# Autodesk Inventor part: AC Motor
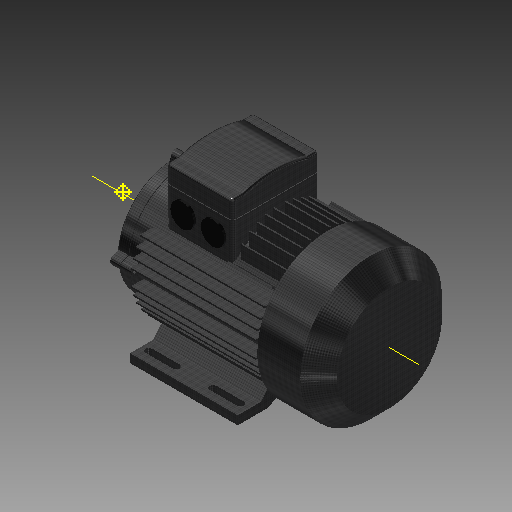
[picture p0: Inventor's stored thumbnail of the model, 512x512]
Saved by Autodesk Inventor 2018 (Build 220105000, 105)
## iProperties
Part Number: AC Motor
Document SubType Name: Modeling
Created: 2003-05
Description: ac-motor.ipt.
Density: 1 g/cm^3
Mass: 2583.35 g
Surface Area: 6107.9 cm^2
Volume: 2583.35 cm^3
Material: Generic
Appearance: Skid Plate
+MSCProtocol1+ProtocolID: P00030526084445659
+MSCProtocol2+Protocol: P00030526084445659<@PID>[Version]<@EL>Version=2.2<@EL>[Baseview]<@EL>InOpt=0<@EL>H2=574<@EL>W2=514<@EL>Top=160<@EL>Left=357<@EL>OnTop=0<@EL>UpdateAll=0<@EL>Enab
Control State: 0
Master: False
Checked Out: False
Shininess: 64.0
Length Units: 11272
Angle Units: 11279
Time Units: 11290
Mass Units: 11286
Length Display Precision: 3
Angle Display Precision: 2
Compacted: True
Density: 0.0
Volumn: 0.0
Area: 0.0
PropertySet Name: Model Information
Author: Autodesk, Inc.
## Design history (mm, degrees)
sketch "Sketch1"
  geometry: L1 (0, 0)-(0, 45); L2 (6, 78)-(220, 78); L3 (220, 78)-(220, 98); L4 (220, 98)-(279.5, 98); L5 (279.5, 98)-(305, 72.5); L6 (305, 72.5)-(305, 0); L7 (305, 0)-(0, 0); L8 (0, 45)-(5, 45); L9 (5, 45)-(5, 60); L10 (5, 60)-(6, 60); L11 (6, 60)-(6, 78); L12 (220, 19)-(-5, 19); L13 (-5, 19)-(-5, 14); L14 (-5, 14)-(-65, 14); L15 (-65, 14)-(-65, 0); L16 (220, 19)-(220, 14); L17 (220, 14)-(279.5, 14); L18 (279.5, 14)-(279.5, 0); L19 (-65, 0)-(305, 0); L20 (305, 0)-(0, 0); L21 (0, 20)-(15, 20); L22 (15, 20)-(15, 68); L23 (15, 68)-(223, 68); L24 (223, 68)-(223, 95); L25 (223, 95)-(278.257, 95); L26 (278.257, 95)-(302, 71.257); L27 (302, 71.257)-(302, 0); L28 (-65, 0)-(279.5, 0); 3 further points
  constraints: 56 end point, 13 parallel, 10 perpendicular, 10 point on line, 3 collinear, 1 vertical, 1 other
  dimensions: "d0" = 196 diameter of L4 L7; "d4" = 63 distance from line of point (63, 0) L1; "d5" = 28 diameter of L14 L7; "d6" = 45 deg angle of L4 L5; "d8" = 60 distance of L13.end L14.end; "d9" = 1 distance between parallel lines of L11 L9; "d10" = 5 distance between parallel lines of L1 L9; "d12" = 5 distance between parallel lines of L13 L1; "d13" = 5 distance between parallel lines of L12 L14; "d17" = 25.5 horizontal distance of L4.end L5.end (derived); "d18" = 3 distance between parallel lines of L6 L27; "d19" = 3 distance between parallel lines of L5 L26; "d20" = 3 distance between parallel lines of L25 L4; "d21" = 3 distance between parallel lines of L3 L24; "d22" = 10 distance between parallel lines of L2 L23; "d23" = 15 distance between parallel lines of L1 L22; "d25" = 1 distance between parallel lines of L12 L21; "d79" = 78 distance between parallel lines of L2 L28 (= d67); "d180" = 25 distance between parallel lines of L8 L21; "d181" = 40 distance between parallel lines of L21 L10; "Size" = 310 distance between parallel lines of L13 L6; "d183" = 85 distance between parallel lines of L6 L3; "d184" = 44 distance from line of L1 point (44, 0); "d185" = 27 distance from line of point (193, 0) L3
revolve "Revolution1" stored, may be unused: angle "d24" = 90 deg
workplane "Work Plane8"
sketch "Sketch3"
  geometry: L1 (-100, 56)-(-100, 98); L2 (-100, 98)-(-88, 98); L3 (-88, 98)-(-88, 66); L4 (-88, 66)-(-63.435, 45.387); L5 (-100, 56)-(-76.489, 15.278); L6 (-76.489, -15.278)-(-100, -56); L7 (-100, -56)-(-100, -98); L8 (-100, -98)-(-88, -98); L9 (-88, -98)-(-88, -66); L10 (-88, -66)-(-63.435, -45.387); A1 r 78 centre (0, 0) between (-63.435, -45.387) and (-63.435, 45.387) reference; 3 further points
  constraints: 20 end point, 4 point on circle, 4 vertical alignment, 3 equal length, 3 parallel, 2 perpendicular, 2 point on line, 1 vertical
  dimensions: "d28" = 42 distance of L1.start L1.end; "d29" = 12 distance of L1.end L2.end; "d30" = 196 distance between parallel lines of L8 L2; "d31" = 20 deg angle of L10 L6; "d33" = 30 deg angle of L6 L7; "d38" = 160 distance of point (-100, -80) point (-100, 80); "d39" = 18 distance from line of L8 point (-100, -80) (= -0.5 x d38 + 0.5 x d30); "d53" = 10 vertical distance of L1.start L3.end (computed from d29); "d54" = 100 distance from line of point (0, 0) L7
extrude "Extrusion1" join sketch "Sketch3" stored distance "d35" = 176 (= d2); taper "d36" = 0 deg
workplane "Work Plane1"
sketch "Sketch2"
  geometry: L1 (49.84, 60)-(128, 60); L2 (128, 60)-(128, 45); L3 (49.84, -60)-(128, -60); L4 (128, -60)-(128, -45); L5 (-120.6, 0)-(177.6, 0) reference; A1 r 148.143 centre (-13.143, 0) between (128, -45) and (128, 45); A2 r 78 centre (0, 0) between (49.84, 60) and (49.84, -60) reference
  constraints: 8 end point, 4 point on circle, 3 perpendicular, 2 point on line, 1 centre point, 1 horizontal, 1 vertical alignment
  dimensions: "d57" = 7 distance edge to line of A1 L2; "d58" = 15 distance of L1.end L2.end; "d60" = 120 distance between parallel lines of L3 L1; "d186" = 128 distance from line of A2.centre L4
extrude "Extrusion2" join sketch "Sketch2" stored distance "d62" = 92 (computed from d27); taper "d63" = 0 deg
sketch "Sketch5"
  geometry: L1 (0, 0)-(92, 0) reference; L2 (0, 0)-(0, -78.16) reference; L3 (-117, -128)-(310, -128) reference; L4 (46, 54)-(46, -275) reference; L5 (67, -50)-(25, -50); C1 r 16.25 at (25, -50); C2 r 16.25 at (67, -50); 2 further points
  constraints: 2 centre point, 2 end point, 2 point on line, 1 equal radius, 1 horizontal alignment, 1 midpoint, 1 parallel, 1 perpendicular
  dimensions: "d61" = 32.5 diameter of C1; "d66" = 42 distance of L5.start L5.end; "d67" = 78 distance from line of L3 L5.end; "d68" = 25 distance from line of L1 point (0, -25)
extrude "Extrusion3" join sketch "Sketch5" distance "d69" = 3; taper "d70" = 0 deg
workplane "Work Plane3"
sketch "Sketch7"
  geometry: L1 (92, 0)-(92, 120) reference; L2 (0, 120)-(0, 0) reference; L3 (0, 120)-(92, 120) reference; L4 (0, 0)-(92, 0) reference; L5 (1, 1)-(1, 119); L6 (1, 119)-(91, 119); L7 (91, 119)-(91, 1); L8 (91, 1)-(1, 1)
  constraints: 8 end point, 3 other
  dimensions: "d75" = 1 distance between parallel lines of L1 L7
extrude "Extrusion4" cut sketch "Sketch7" stored distance "d76" = 1; taper "d77" = 0 deg
workplane "Work Plane4"
sketch "Sketch8"
  geometry: C1 r 78 at (0, 0) reference; C2 r 77 at (0, 0)
  constraints: 1 centre point
  dimensions: "d81" = 1 radial gap between concentric circles of C1 C2
extrude "Extrusion5" cut sketch "Sketch8" stored distance "d82" = 1; taper "d83" = 0 deg
sketch "Sketch10"
  geometry: L1 (-5.796, 85.553)-(-7.928, 77.596); L2 (5.796, 85.553)-(7.928, 77.596); C1 r 77 at (0, 0) reference; A1 r 78 centre (0, 0) between (-7.928, 77.596) and (7.928, 77.596) reference; A2 r 6 centre (0, 84) between (5.796, 85.553) and (-5.796, 85.553); 1 further point
  constraints: 7 point on circle, 4 end point, 2 point on line, 2 tangent, 2 vertical alignment, 1 centre point, 1 horizontal alignment
  dimensions: "d89" = 6 radius of A2; "d90" = 6 distance of point (0, 78) A2.centre; "d91" = 30 deg angle of L2 L1
extrude "Extrusion7" join sketch "Sketch10" distance "d92" = 15; taper "d93" = 0 deg
sketch "Sketch11"
  geometry: L1 (5.796, 85.553)-(7.928, 77.596) reference; L2 (-7.928, 77.596)-(-5.796, 85.553) reference; A1 r 78 centre (0, 0) between (7.928, 77.596) and (-7.928, 77.596) reference; A2 r 6 centre (0, 84) between (5.796, 85.553) and (-5.796, 85.553) reference
extrude "Extrusion8" join sketch "Sketch11" distance "d94" = 13 (computed from d80); taper "d95" = 0 deg
sketch "Sketch12"
  geometry: A1 r 6 centre (0, 84) between (5.796, 85.553) and (-5.796, 85.553) reference
hole "Hole2" sketch "Sketch12" at (0, 84) diameter "d96" = 6; stored, may be unused: countersink angle "d100" = 82 deg, drill point angle "d102" = 118 deg; dims "d97" = 6, "d98" = 4, "d99" = 2, "d101" = 8
pattern_circular "Circular Pattern1" dims angle "d105" = 360 deg
fillet "Fillet1" dims "d106" = 2, "d188" = -10 (derived)
workplane "Work Plane5"
workplane "Work Plane6"
sketch "Sketch13"
  geometry: L1 (77.356, 10)-(95.071, 10); L2 (95.071, 10)-(95.071, 12); L3 (95.071, 12)-(77.071, 12); L4 (75.078, 21.15)-(92.793, 21.15); L5 (92.793, 21.15)-(92.793, 23.15); L6 (92.793, 23.15)-(74.485, 23.15); L7 (70.998, 32.3)-(88.713, 32.3); L8 (88.713, 32.3)-(88.713, 34.3); L9 (88.713, 34.3)-(70.054, 34.3); L10 (64.777, 43.45)-(82.492, 43.45); L11 (82.492, 43.45)-(82.492, 45.45); L12 (82.492, 45.45)-(63.39, 45.45); L13 (77.356, -10)-(95.071, -10); L14 (95.071, -10)-(95.071, -12); L15 (95.071, -12)-(77.071, -12); L16 (75.078, -21.15)-(92.485, -21.15); L17 (92.485, -21.15)-(92.485, -23.15); L18 (92.485, -23.15)-(74.485, -23.15); L19 (70.998, -32.3)-(88.054, -32.3); L20 (88.054, -32.3)-(88.054, -34.3); L21 (88.054, -34.3)-(70.054, -34.3); L22 (64.777, -43.45)-(81.39, -43.45); L23 (81.39, -43.45)-(81.39, -45.45); L24 (81.39, -45.45)-(63.39, -45.45); L25 (55.703, -54.6)-(71.67, -54.6); L26 (71.67, -54.6)-(71.67, -56.6); L27 (71.67, -56.6)-(53.67, -56.6); 1 further point
  constraints: 54 end point, 16 parallel, 11 equal length, 10 perpendicular, 1 horizontal, 1 vertical alignment, 19 other
  dimensions: "d110" = 2 distance of L1.end L2.end; "d112" = 10 distance from line of L1 point (0, 0); "d118" = 10 distance from line of L13 point (0, 0); "d122" = 18 distance of L17.end L18.end (= d123); "d123" = 18 distance of L14.end L15.end (computed from d67, d0); "d124" = 18 distance of L20.end L21.end (= d123); "d125" = 18 distance of L23.end L24.end (= d123); "d131" = 18 distance of L26.end L27.end (= d123); "d149" = 11.15 distance between parallel lines of L4 L1 (computed from d67); "d150" = 11.15 distance between parallel lines of L7 L4 (= d149); "d151" = 11.15 distance between parallel lines of L10 L7 (= d149); "d152" = 11.15 distance between parallel lines of L16 L13 (= d149); "d153" = 11.15 distance between parallel lines of L19 L16 (= d149); "d154" = 11.15 distance between parallel lines of L22 L19 (= d149); "d155" = 11.15 distance between parallel lines of L25 L22 (= d149)
extrude "Extrusion9" join sketch "Sketch13" stored distance "d108" = 10; taper "d109" = 0 deg
workplane "Work Plane7"
sketch "Sketch14"
  geometry: L1 (7, 77.685)-(7, 95.685); L2 (7, 95.685)-(9, 95.685); L3 (9, 95.685)-(9, 77.479); L4 (18.15, 75.859)-(18.15, 93.559); L5 (18.15, 93.559)-(20.15, 93.559); L6 (20.15, 93.559)-(20.15, 75.352); L7 (29.3, 72.288)-(29.3, 89.651); L8 (29.3, 89.651)-(31.3, 89.651); L9 (31.3, 89.651)-(31.3, 71.444); L10 (40.45, 66.692)-(40.45, 84.692); L11 (40.45, 84.692)-(42.45, 84.692); L12 (42.45, 84.692)-(42.45, 65.437); L13 (51.6, 58.493)-(51.6, 74.872); L14 (51.6, 74.872)-(53.6, 74.872); L15 (53.6, 74.872)-(53.6, 56.666); 1 further point
  constraints: 30 end point, 15 parallel, 6 perpendicular, 1 vertical, 11 other
  dimensions: "d132" = 7 distance from line of point (0, 0) L1; "d134" = 2 distance between parallel lines of L3 L1; "d138" = 18 distance of L1.start L1.end (= d123); "d156" = 11.15 distance between parallel lines of L4 L1 (= d149); "d157" = 11.15 distance between parallel lines of L7 L4 (= d149); "d158" = 11.15 distance between parallel lines of L10 L7 (= d149); "d159" = 11.15 distance between parallel lines of L13 L10 (= d149); "d178" = 18 distance of L10.start L10.end (= d123)
extrude "Extrusion10" join sketch "Sketch14" stored distance "d140" = 10; taper "d141" = 0 deg
sketch "Sketch15"
  geometry: L1 (53.6, 56.666)-(63.39, 45.45); L2 (58.101, 52.041)-(71.662, 63.878); L3 (71.662, 63.878)-(72.977, 62.371); L4 (72.977, 62.371)-(59.416, 50.535); L5 (58.495, 51.058)-(72.319, 63.125); A1 r 78 centre (0, 0) between (53.6, 56.666) and (63.39, 45.45) reference
  constraints: 10 end point, 2 midpoint, 2 parallel, 2 point on circle, 1 perpendicular, 1 point on line
  dimensions: "d146" = 2 distance of L2.end L3.end; "d160" = 18 distance of L3.end L4.end (= d123)
extrude "Extrusion11" join sketch "Sketch15" stored distance "d147" = 10; taper "d148" = 0 deg
mirror "Mirror4"
fillet "Fillet2" dims "d142" = 5, "d189" = -10 (derived)
fillet "Fillet3" dims "d143" = 4, "d190" = -10 (derived)
fillet "Fillet4" dims "d144" = 2, "d145" = 4, "d191" = -10 (derived)
workpoint "Work Point1"
sketch "Sketch19"
  geometry: L1 (0, 0)-(149, 0) reference; L2 (10.254, 11.113)-(48.354, 11.113); L3 (48.354, 11.113)-(48.354, 20.638); L4 (48.354, 20.638)-(10.254, 20.637); L5 (10.254, 20.637)-(10.254, 11.113); 2 further points
  constraints: 8 end point, 2 midpoint, 2 parallel, 2 vertical alignment, 1 horizontal, 1 perpendicular, 4 other
  dimensions: "d194" = 15.875 distance from line of L1 point (10.254, 15.875); "d195" = 9.525 distance between parallel lines of L4 L2; "d196" = 38.1 distance between parallel lines of L3 L5
extrude "Extrusion13" cut sketch "Sketch19" extent not by distance; stored distance "d197" = 10; taper "d198" = 0 deg
pattern_linear "Rectangular Pattern2" dims "d201" = 88.9, "d204" = 165.1
workaxis "Work Axis2"
body "Solid1"
workplane "Work Plane"
other parameters: "d2" = 176, "d3" = 23 (= -0.5 x d1 + 0.5 x d37), "d7" = 372, "d27" = 102, "d37" = 186 (computed from d2), "d80" = -16, "d107" = 5, "d117" = 5, "d139" = 5
